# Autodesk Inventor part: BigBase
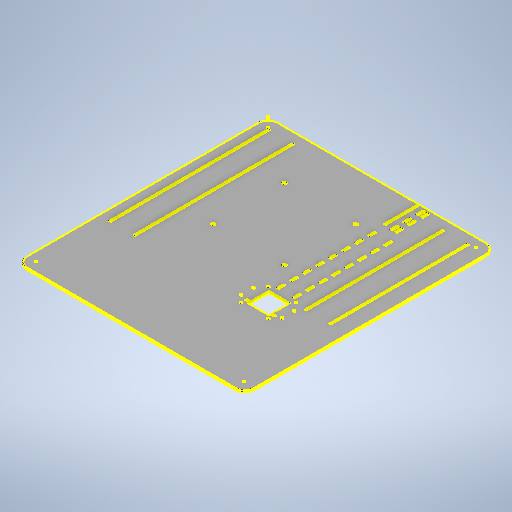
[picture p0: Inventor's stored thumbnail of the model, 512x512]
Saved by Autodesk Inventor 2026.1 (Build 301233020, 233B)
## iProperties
Created: 2026-10
Part Number: BigBase
Material: Generic
Document SubType Name: Modeling
Designer: hp
Density: 1 g/cm^3
Appearance: Default
Author: hp
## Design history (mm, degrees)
sketch "BigBaseSketch"
  geometry: L1 (0, 0)-(1200, 0); L2 (1200, 0)-(1200, 700); L3 (1200, 700)-(0, 700); L4 (0, 700)-(0, 0); L5 (378, 191.5)-(141, 191.5); L6 (141, 191.5)-(141, 428.5); L7 (141, 428.5)-(378, 428.5); L8 (378, 428.5)-(378, 191.5); L9 (378, 191.5)-(141, 428.5); L10 (141, 191.5)-(378, 428.5); L11 (259.5, 191.5)-(259.5, 428.5); L12 (378, 310)-(141, 310); L13 (141, 310)-(378, 310); C1 r 5 at (150, 200.5); C2 r 5 at (150, 419.5); C3 r 5 at (369, 200.5); C4 r 5 at (369, 419.5); 1 further point
  constraints: 26 end point, 5 midpoint, 5 symmetric about line, 4 centre point, 4 parallel, 2 horizontal, 2 perpendicular, 1 point on line, 3 other
  dimensions: "d0" = 1200 distance of L3.end L2.end; "d236" = 237 distance of L6.end L7.end; "d237" = 237 distance of L5.end L6.end; "d242" = 10 diameter of C1; "d243" = 9 distance from line of L5 C1.centre; "d245" = 150 distance from line of L4 C1.centre; "d252" = 700 distance of L3.end L1.start; "d253" = 40 vertical distance of point (0, 350) L12.end
extrude "Extrusion2" new body sketch "BigBaseSketch" distance "d14" = 5; taper "d15" = 0 deg
sketch "Sketch3"
  geometry: L1 (31, -10)-(31, 630); L2 (31, 106.5)-(521, 106.5); L3 (521, 106.5)-(521, 111.5); L4 (521, 111.5)-(31, 111.5); L5 (31, 111.5)-(31, 106.5); L6 (31, 31.5)-(521, 31.5); L7 (521, 31.5)-(521, 36.5); L8 (521, 36.5)-(31, 36.5); L9 (31, 36.5)-(31, 31.5); L10 (31, 568.5)-(456, 568.5); L11 (456, 568.5)-(456, 573.5); L12 (456, 573.5)-(31, 573.5); L13 (31, 573.5)-(31, 568.5); L14 (31, 643.5)-(456, 643.5); L15 (456, 648.5)-(31, 648.5); L16 (456, 643.5)-(456, 648.5); L17 (31, 648.5)-(31, 643.5); L18 (378, 191.5)-(141, 191.5) reference; L19 (141, 191.5)-(141, 428.5) reference; L20 (141, 428.5)-(378, 428.5) reference; L21 (378, 428.5)-(378, 191.5) reference; L22 (259.5, 191.5)-(259.5, 428.5) reference; L23 (0, 700)-(0, 0) reference; L24 (131, 468.5)-(461, 468.5); L25 (461, 468.5)-(461, 523.5); L26 (461, 523.5)-(131, 523.5); L27 (131, 523.5)-(131, 468.5); L28 (131, 468.5)-(461, 468.5); L29 (461, 468.5)-(461, 473.5); L30 (461, 473.5)-(131, 473.5); L31 (131, 473.5)-(131, 468.5); L32 (131, 523.5)-(461, 523.5); L33 (461, 523.5)-(461, 518.5); L34 (461, 518.5)-(131, 518.5); L35 (131, 518.5)-(131, 523.5); 3 further points; 2 other entities
  constraints: 58 end point, 14 parallel, 7 horizontal, 7 perpendicular, 4 collinear, 2 midpoint, 2 point on line, 1 horizontal alignment, 2 other
  dimensions: "d64" = 640 distance of L1.end L1.start; "d129" = 490 distance of L4.end L3.end; "d130" = 5 distance of L3.end L2.end; "d133" = 490 distance of L8.end L7.end (derived); "d134" = 5 distance of L7.end L6.end; "d135" = 70 distance between parallel lines of L2 L8; "d138" = 425 distance of L12.end L11.end; "d139" = 5 distance of L11.end L10.end; "d140" = 425 distance of L15.end L15.start (derived); "d141" = 5 distance of L15.start L14.end; "d144" = 70 distance between parallel lines of L12 L14; "d248" = 80 distance between parallel lines of L4 L18; "d249" = 140 distance between parallel lines of L20 L10; "d251" = 31 distance between parallel lines of L1 L23; "d259" = 330 distance of L26.end L25.end; "d260" = 55 distance of L25.end L24.end; "d261" = 40 distance between parallel lines of L20 L24; "d262" = 5 distance between parallel lines of L11 L25; "d263" = 5 distance of L29.end L28.end; "d264" = 5 distance of L32.end L33.end
extrude "Extrusion3" cut sketch "Sketch3" extent not by distance; stored distance "d101" = 0; taper "d102" = 0 deg
sketch "Sketch20"
  geometry: 4 further points
hole "Hole8" sketch "Sketch20" at (-477, 433.5), (-515, 433.5), (-477, 558.5), (-515, 558.5) diameter "d331" = 4.5; stored, may be unused: countersink angle "d335" = 90 deg, drill point angle "d337" = 0 deg; dims "d332" = 6, "d333" = 4, "d334" = 2, "d336" = 8
sketch "Sketch4"
  geometry: L1 (526, 463.5)-(526, 528.5); L2 (526, 528.5)-(461, 528.5); L3 (461, 528.5)-(461, 463.5); L4 (461, 463.5)-(526, 463.5); L5 (378, 428.5)-(378, 191.5) reference; L6 (378, 191.5)-(141, 191.5) reference; L7 (461, 468.5)-(461, 523.5) reference; 1 further point
  constraints: 8 end point, 2 parallel, 1 perpendicular
  dimensions: "d119" = 65 distance of L3.end L2.end; "d120" = 65 distance of L2.end L1.end; "d330" = 83 distance between parallel lines of L5 L3
extrude "Extrusion4" cut sketch "Sketch4" extent not by distance; stored distance "d112" = 0; taper "d113" = 0 deg
fillet "Fillet1" dims "d147" = 30
extrude "Extrusion7" cut sketch "BigBaseSketch" distance "d246" = 5; taper "d247" = 0 deg
sketch "Sketch16"
  geometry: L1 (131, 468.5)-(461, 468.5) reference; L2 (461, 473.5)-(131, 473.5) reference; L3 (461, 518.5)-(131, 518.5) reference; L4 (131, 523.5)-(461, 523.5) reference; L5 (131, 523.5)-(131, 468.5) reference; L6 (461, 468.5)-(461, 523.5) reference; L7 (141, 468.5)-(161, 468.5); L8 (161, 468.5)-(161, 473.5); L9 (161, 473.5)-(141, 473.5); L10 (141, 473.5)-(141, 468.5); L11 (141, 518.5)-(161, 518.5); L12 (161, 518.5)-(161, 523.5); L13 (161, 523.5)-(141, 523.5); L14 (141, 523.5)-(141, 518.5); L15 (181, 473.5)-(181, 468.5); L16 (181, 468.5)-(201, 468.5); L17 (201, 473.5)-(181, 473.5); L18 (201, 468.5)-(201, 473.5); L19 (181, 518.5)-(201, 518.5); L20 (181, 523.5)-(181, 518.5); L21 (201, 518.5)-(201, 523.5); L22 (201, 523.5)-(181, 523.5); L23 (221, 473.5)-(221, 468.5); L24 (221, 468.5)-(241, 468.5); L25 (241, 473.5)-(221, 473.5); L26 (241, 468.5)-(241, 473.5); L27 (221, 518.5)-(241, 518.5); L28 (221, 523.5)-(221, 518.5); L29 (241, 518.5)-(241, 523.5); L30 (241, 523.5)-(221, 523.5); L31 (261, 473.5)-(261, 468.5); L32 (261, 468.5)-(281, 468.5); L33 (281, 473.5)-(261, 473.5); L34 (281, 468.5)-(281, 473.5); L35 (261, 518.5)-(281, 518.5); L36 (261, 523.5)-(261, 518.5); L37 (281, 518.5)-(281, 523.5); L38 (281, 523.5)-(261, 523.5); L39 (301, 473.5)-(301, 468.5); L40 (301, 468.5)-(321, 468.5); L41 (321, 473.5)-(301, 473.5); L42 (321, 468.5)-(321, 473.5); L43 (301, 518.5)-(321, 518.5); L44 (301, 523.5)-(301, 518.5); L45 (321, 518.5)-(321, 523.5); L46 (321, 523.5)-(301, 523.5); L47 (341, 473.5)-(341, 468.5); L48 (341, 468.5)-(361, 468.5); L49 (361, 473.5)-(341, 473.5); L50 (361, 468.5)-(361, 473.5); L51 (341, 518.5)-(361, 518.5); L52 (341, 523.5)-(341, 518.5); L53 (361, 518.5)-(361, 523.5); L54 (361, 523.5)-(341, 523.5); L55 (381, 473.5)-(381, 468.5); L56 (381, 468.5)-(401, 468.5); L57 (401, 473.5)-(381, 473.5); L58 (401, 468.5)-(401, 473.5); L59 (381, 518.5)-(401, 518.5); L60 (381, 523.5)-(381, 518.5); L61 (401, 518.5)-(401, 523.5); L62 (401, 523.5)-(381, 523.5); L63 (421, 473.5)-(421, 468.5); L64 (421, 468.5)-(441, 468.5)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; 1 further point
  constraints: 128 end point, 4 parallel, 4 point on line, 3 horizontal, 2 perpendicular, 1 collinear, 112 other
  dimensions: "d274" = 20 distance of L9.end L8.end; "d275" = 10 distance between parallel lines of L5 L10; "d276" = 20 distance of L13.end L12.end; "d279" = 40 distance of L7.start L15.end
extrude "Extrusion8" cut sketch "Sketch16" distance "d284" = 5; taper "d285" = 0 deg
sketch "Sketch17"
  geometry: L1 (461, 528.5)-(526, 528.5) reference; L2 (461, 463.5)-(461, 528.5) reference; L3 (526, 528.5)-(526, 463.5) reference; L4 (526, 463.5)-(461, 463.5) reference; L5 (1170, 700)-(30, 700) reference; L6 (461, 700)-(526, 700); L7 (526, 700)-(526, 800); L8 (526, 800)-(461, 800); L9 (461, 800)-(461, 700); L10 (491.3, 590)-(498.5, 590); L11 (498.5, 590)-(498.5, 767); L12 (498.5, 767)-(491.3, 767); L13 (491.3, 767)-(491.3, 590); L14 (0, 492.4)-(121, 492.4); L15 (121, 492.4)-(121, 499.6); L16 (121, 499.6)-(0, 499.6); L17 (0, 499.6)-(0, 492.4); L18 (131, 523.5)-(131, 468.5) reference; L19 (0, 670)-(0, 30) reference; L20 (0, 499.6)-(121, 499.6); L21 (121, 499.6)-(121, 505.6); L22 (121, 505.6)-(0, 505.6); L23 (0, 505.6)-(0, 499.6); L24 (0, 492.4)-(121, 492.4); L25 (121, 492.4)-(121, 486.4); L26 (121, 486.4)-(0, 486.4); L27 (0, 486.4)-(0, 492.4); 6 further points
  constraints: 40 end point, 10 parallel, 5 horizontal, 5 perpendicular, 4 midpoint, 3 point on line, 1 collinear, 1 horizontal alignment
  dimensions: "d288" = 100 distance of L7.end L6.end; "d291" = 7.2 distance of L12.end L11.end; "d294" = 33 distance between parallel lines of L8 L12; "d295" = 210 distance from line of point (493.5, 800) L10; "d298" = 31.1 distance from line of L3 point (494.9, 590) (derived); "d306" = 7.2 distance of L15.end L14.end; "d307" = 10 distance of point (131, 496) point (121, 496); "d308" = 6 distance of L21.end L20.end; "d309" = 6 distance of L24.end L25.end (derived)
sketch "Sketch19"
  geometry: L1 (0, 670)-(0, 30) reference; L2 (121, 486.4)-(0, 486.4) reference; L3 (121, 505.6)-(0, 505.6) reference; L4 (121, 499.6)-(0, 499.6) reference; L5 (0, 492.4)-(121, 492.4) reference; L6 (121, 492.4)-(121, 486.4) reference; L7 (121, 499.6)-(121, 505.6) reference; L8 (10, 486.4)-(30, 486.4); L9 (30, 486.4)-(30, 492.4); L10 (30, 492.4)-(10, 492.4); L11 (10, 492.4)-(10, 486.4); L12 (10, 499.6)-(30, 499.6); L13 (30, 499.6)-(30, 505.6); L14 (30, 505.6)-(10, 505.6); L15 (10, 505.6)-(10, 499.6); L16 (10.1, 486.4)-(29.9, 486.4); L17 (29.9, 486.4)-(29.9, 492.4); L18 (29.9, 492.4)-(10.1, 492.4); L19 (10.1, 492.4)-(10.1, 486.4); L20 (10.1, 499.6)-(29.9, 499.6); L21 (29.9, 499.6)-(29.9, 505.6); L22 (29.9, 505.6)-(10.1, 505.6); L23 (10.1, 505.6)-(10.1, 499.6); L24 (50.1, 492.4)-(50.1, 486.4); L25 (50.1, 486.4)-(69.9, 486.4); L26 (50, 492.4)-(50, 486.4); L27 (50, 486.4)-(70, 486.4); L28 (69.9, 499.6)-(69.9, 505.6); L29 (70, 499.6)-(70, 505.6); L30 (69.9, 492.4)-(50.1, 492.4); L31 (70, 492.4)-(50, 492.4); L32 (50.1, 499.6)-(69.9, 499.6); L33 (50, 499.6)-(70, 499.6); L34 (69.9, 505.6)-(50.1, 505.6); L35 (70, 505.6)-(50, 505.6); L36 (50.1, 505.6)-(50.1, 499.6); L37 (50, 505.6)-(50, 499.6); L38 (69.9, 486.4)-(69.9, 492.4); L39 (70, 486.4)-(70, 492.4); L40 (90.1, 492.4)-(90.1, 486.4); L41 (90.1, 486.4)-(109.9, 486.4); L42 (90, 492.4)-(90, 486.4); L43 (90, 486.4)-(110, 486.4); L44 (109.9, 499.6)-(109.9, 505.6); L45 (110, 499.6)-(110, 505.6); L46 (109.9, 492.4)-(90.1, 492.4); L47 (110, 492.4)-(90, 492.4); L48 (90.1, 499.6)-(109.9, 499.6); L49 (90, 499.6)-(110, 499.6); L50 (109.9, 505.6)-(90.1, 505.6); L51 (110, 505.6)-(90, 505.6); L52 (90.1, 505.6)-(90.1, 499.6); L53 (90, 505.6)-(90, 499.6); L54 (109.9, 486.4)-(109.9, 492.4); L55 (110, 486.4)-(110, 492.4); 13 further points
  constraints: 96 end point, 8 parallel, 8 point on line, 5 horizontal, 4 midpoint, 4 perpendicular, 3 collinear, 2 coincident, 71 other
  dimensions: "d310" = 20 distance of L10.end L9.end; "d311" = 10 distance between parallel lines of L1 L11; "d321" = 19.8 distance of L18.end L17.end; "d322" = 19.8 distance of L22.end L21.end; "d325" = 40 distance of point (20, 492.4) point (60, 492.4)
extrude "Extrusion11" cut sketch "Sketch19" stored distance "d319" = 10; taper "d320" = 0 deg
sketch "Sketch21"
  geometry: L1 (1170, 700)-(30, 700) reference; L2 (1201.62, 0)-(771, 0); L3 (771, 0)-(771, 700); L4 (771, 700)-(1201.62, 700); L5 (1201.62, 700)-(1201.62, 0); L6 (521, 111.5)-(521, 106.5) reference; 2 further points
  constraints: 8 end point, 2 parallel, 1 horizontal, 1 perpendicular, 1 point on line
  dimensions: "d340" = 250 distance between parallel lines of L3 L6
extrude "Extrusion12" cut sketch "Sketch21" distance "d338" = 10; taper "d339" = 0 deg
fillet "Fillet2" dims "d341" = 30
sketch "Sketch22"
  geometry: L1 (5, 462.5)-(105, 462.5); L2 (105, 462.5)-(105, 467.5); L3 (105, 467.5)-(5, 467.5); L4 (5, 467.5)-(5, 462.5); L5 (0, 670)-(0, 30) reference; L6 (29.9, 486.4)-(10.1, 486.4) reference; 2 further points
  constraints: 8 end point, 2 parallel, 1 horizontal, 1 midpoint, 1 perpendicular
  dimensions: "d342" = 100 distance of L3.end L2.end; "d343" = 5 distance of L2.end L1.end; "d344" = 5 distance from line of L5 point (5, 465); "d345" = 18.9 distance between parallel lines of L6 L3
extrude "Extrusion13" cut sketch "Sketch22" distance "d346" = 5; taper "d347" = 0 deg
sketch "Sketch23"
  geometry: 4 further points
hole "Hole9" sketch "Sketch23" at (536, 538.5), (451, 538.5), (451, 453.5), (536, 453.5) diameter "d348" = 4.5; stored, may be unused: countersink angle "d352" = 90 deg, drill point angle "d354" = 0 deg; dims "d349" = 6, "d350" = 4, "d351" = 2, "d353" = 8
sketch "Sketch24"
  geometry: L1 (-105, 467.5)-(-5, 467.5) reference; L2 (-5, 467.5)-(-5, 462.5) reference; L3 (-5, 462.5)-(-105, 462.5) reference; L4 (-105, 462.5)-(-105, 467.5) reference; L5 (-771, 670)-(-771, 30) reference; L6 (-30, 0)-(-741, 0) reference; L7 (0, 670)-(0, 30) reference; L8 (-741, 700)-(-30, 700) reference; L9 (-69.9, 505.6)-(-50.1, 505.6) reference; L10 (-50.1, 505.6)-(-50.1, 499.6) reference; L11 (-50.1, 499.6)-(-69.9, 499.6) reference; L12 (-69.9, 499.6)-(-69.9, 505.6) reference; L13 (-109.9, 499.6)-(-109.9, 505.6) reference; L14 (-109.9, 505.6)-(-90.1, 505.6) reference; L15 (-90.1, 505.6)-(-90.1, 499.6) reference; L16 (-90.1, 499.6)-(-109.9, 499.6) reference; L17 (-90.1, 486.4)-(-109.9, 486.4) reference; L18 (-109.9, 486.4)-(-109.9, 492.4) reference; L19 (-109.9, 492.4)-(-90.1, 492.4) reference; L20 (-90.1, 492.4)-(-90.1, 486.4) reference; L21 (-10.1, 499.6)-(-29.9, 499.6) reference; L22 (-29.9, 499.6)-(-29.9, 505.6) reference; L23 (-29.9, 505.6)-(-10.1, 505.6) reference; L24 (-10.1, 505.6)-(-10.1, 499.6) reference; L25 (-50.1, 486.4)-(-69.9, 486.4) reference; L26 (-69.9, 486.4)-(-69.9, 492.4) reference; L27 (-69.9, 492.4)-(-50.1, 492.4) reference; L28 (-50.1, 492.4)-(-50.1, 486.4) reference; L29 (-10.1, 486.4)-(-29.9, 486.4) reference; L30 (-29.9, 486.4)-(-29.9, 492.4) reference; L31 (-29.9, 492.4)-(-10.1, 492.4) reference; L32 (-10.1, 492.4)-(-10.1, 486.4) reference; L33 (-321, 468.5)-(-321, 473.5) reference; L34 (-321, 473.5)-(-301, 473.5) reference; L35 (-301, 473.5)-(-301, 468.5) reference; L36 (-301, 468.5)-(-321, 468.5) reference; L37 (-361, 468.5)-(-361, 473.5) reference; L38 (-361, 473.5)-(-341, 473.5) reference; L39 (-341, 473.5)-(-341, 468.5) reference; L40 (-341, 468.5)-(-361, 468.5) reference; L41 (-401, 468.5)-(-401, 473.5) reference; L42 (-401, 473.5)-(-381, 473.5) reference; L43 (-381, 473.5)-(-381, 468.5) reference; L44 (-381, 468.5)-(-401, 468.5) reference; L45 (-441, 468.5)-(-441, 473.5) reference; L46 (-441, 473.5)-(-421, 473.5) reference; L47 (-421, 473.5)-(-421, 468.5) reference; L48 (-421, 468.5)-(-441, 468.5) reference; L49 (-161, 523.5)-(-141, 523.5) reference; L50 (-141, 523.5)-(-141, 518.5) reference; L51 (-141, 518.5)-(-161, 518.5) reference; L52 (-161, 518.5)-(-161, 523.5) reference; L53 (-201, 523.5)-(-181, 523.5) reference; L54 (-181, 523.5)-(-181, 518.5) reference; L55 (-181, 518.5)-(-201, 518.5) reference; L56 (-201, 518.5)-(-201, 523.5) reference; L57 (-241, 523.5)-(-221, 523.5) reference; L58 (-221, 523.5)-(-221, 518.5) reference; L59 (-221, 518.5)-(-241, 518.5) reference; L60 (-241, 518.5)-(-241, 523.5) reference; L61 (-281, 523.5)-(-261, 523.5) reference; L62 (-261, 523.5)-(-261, 518.5) reference; L63 (-261, 518.5)-(-281, 518.5) reference; L64 (-281, 518.5)-(-281, 523.5) reference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; C1 r 2.25 at (-536, 453.5) reference; C2 r 2.25 at (-451, 453.5) reference; C3 r 2.25 at (-451, 538.5) reference; C4 r 2.25 at (-536, 538.5) reference; C5 r 5 at (-369, 200.5) reference; C6 r 5 at (-150, 419.5) reference; C7 r 5 at (-369, 419.5) reference; C8 r 5 at (-150, 200.5) reference; C9 r 2.25 at (-515, 558.5) reference; C10 r 2.25 at (-477, 558.5) reference; C11 r 2.25 at (-515, 433.5) reference; C12 r 2.25 at (-477, 433.5) reference; A1 r 30 centre (-741, 670) between (-741, 700) and (-771, 670) reference; A2 r 30 centre (-741, 30) between (-771, 30) and (-741, 0) reference; A3 r 30 centre (-30, 30) between (-30, 0) and (0, 30) reference; A4 r 30 centre (-30, 670) between (0, 670) and (-30, 700) reference; 1 further point
  node "Projected Loop2"
sketch "Sketch25"
  geometry: L1 (526, 528.5)-(526, 463.5) reference; L2 (526, 463.5)-(461, 463.5) reference; L3 (461, 528.5)-(526, 528.5) reference; L4 (461, 463.5)-(461, 528.5) reference; L5 (521, 461)-(516, 461); L6 (516, 461)-(516, 451.2); L7 (516, 451.2)-(521, 451.2); L8 (521, 451.2)-(521, 461); L9 (516, 531)-(521, 531); L10 (521, 531)-(521, 540.8); L11 (521, 540.8)-(516, 540.8); L12 (516, 540.8)-(516, 531); 1 further point
  constraints: 16 end point, 4 parallel, 2 horizontal, 2 perpendicular, 2 point on line
  dimensions: "d355" = 5 distance of L7.end L6.end; "d356" = 9.8 distance of L6.end L5.end; "d357" = 9.8 distance of L10.end L9.end; "d358" = 5 distance between parallel lines of L1 L10; "d359" = 2.5 distance between parallel lines of L3 L9; "d360" = 2.5 distance between parallel lines of L5 L2 (derived)
extrude "Extrusion14" cut sketch "Sketch25" stored distance "d361" = 5; taper "d362" = 0 deg
sketch "Sketch26"
  geometry: L1 (521, 540.8)-(521, 531) reference; L2 (521, 531)-(516, 531) reference; L3 (516, 531)-(516, 540.8) reference; L4 (516, 540.8)-(521, 540.8) reference; L5 (516, 461)-(521, 461) reference; L6 (521, 461)-(521, 451.2) reference; L7 (521, 451.2)-(516, 451.2) reference; L8 (516, 451.2)-(516, 461) reference; L9 (5, 467.5)-(105, 467.5) reference; L10 (105, 467.5)-(105, 462.5) reference; L11 (105, 462.5)-(5, 462.5) reference; L12 (5, 462.5)-(5, 467.5) reference; L13 (31, 573.5)-(456, 573.5) reference; L14 (456, 573.5)-(456, 568.5) reference; L15 (456, 568.5)-(31, 568.5) reference; L16 (31, 568.5)-(31, 573.5) reference; L17 (31, 111.5)-(521, 111.5) reference; L18 (521, 111.5)-(521, 106.5) reference; L19 (521, 106.5)-(31, 106.5) reference; L20 (31, 106.5)-(31, 111.5) reference; L21 (31, 648.5)-(456, 648.5) reference; L22 (456, 648.5)-(456, 643.5) reference; L23 (456, 643.5)-(31, 643.5) reference; L24 (31, 643.5)-(31, 648.5) reference; L25 (31, 36.5)-(521, 36.5) reference; L26 (521, 36.5)-(521, 31.5) reference; L27 (521, 31.5)-(31, 31.5) reference; L28 (31, 31.5)-(31, 36.5) reference; L29 (461, 463.5)-(461, 528.5) reference; L30 (461, 528.5)-(526, 528.5) reference; L31 (526, 528.5)-(526, 463.5) reference; L32 (526, 463.5)-(461, 463.5) reference; L33 (741, 700)-(30, 700) reference; L34 (0, 670)-(0, 30) reference; L35 (30, 0)-(741, 0) reference; L36 (771, 30)-(771, 670) reference; L37 (421, 523.5)-(441, 523.5) reference; L38 (441, 523.5)-(441, 518.5) reference; L39 (441, 518.5)-(421, 518.5) reference; L40 (421, 518.5)-(421, 523.5) reference; L41 (301, 523.5)-(321, 523.5) reference; L42 (321, 523.5)-(321, 518.5) reference; L43 (321, 518.5)-(301, 518.5) reference; L44 (301, 518.5)-(301, 523.5) reference; L45 (341, 523.5)-(361, 523.5) reference; L46 (361, 523.5)-(361, 518.5) reference; L47 (361, 518.5)-(341, 518.5) reference; L48 (341, 518.5)-(341, 523.5) reference; L49 (381, 523.5)-(401, 523.5) reference; L50 (401, 523.5)-(401, 518.5) reference; L51 (401, 518.5)-(381, 518.5) reference; L52 (381, 518.5)-(381, 523.5) reference; L53 (141, 473.5)-(161, 473.5) reference; L54 (161, 473.5)-(161, 468.5) reference; L55 (161, 468.5)-(141, 468.5) reference; L56 (141, 468.5)-(141, 473.5) reference; L57 (201, 473.5)-(201, 468.5) reference; L58 (201, 468.5)-(181, 468.5) reference; L59 (181, 468.5)-(181, 473.5) reference; L60 (181, 473.5)-(201, 473.5) reference; L61 (241, 473.5)-(241, 468.5) reference; L62 (241, 468.5)-(221, 468.5) reference; L63 (221, 468.5)-(221, 473.5) reference; L64 (221, 473.5)-(241, 473.5) reference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; C1 r 2.25 at (536, 453.5) reference; C2 r 2.25 at (451, 453.5) reference; C3 r 2.25 at (451, 538.5) reference; C4 r 2.25 at (536, 538.5) reference; C5 r 2.25 at (477, 433.5) reference; C6 r 2.25 at (515, 433.5) reference; C7 r 2.25 at (477, 558.5) reference; C8 r 2.25 at (515, 558.5) reference; C9 r 5 at (150, 200.5) reference; C10 r 5 at (369, 419.5) reference; C11 r 5 at (150, 419.5) reference; C12 r 5 at (369, 200.5) reference; A1 r 30 centre (741, 670) between (771, 670) and (741, 700) reference; A2 r 30 centre (30, 670) between (30, 700) and (0, 670) reference; A3 r 30 centre (30, 30) between (0, 30) and (30, 0) reference; A4 r 30 centre (741, 30) between (741, 0) and (771, 30) reference; 1 further point
  node "Projected Loop3"
body "Solid2"
node "Sketch Rectangular Pattern6" dims "d279" = 40, "d282" = 10
node "Sketch Rectangular Pattern8" dims "d325" = 40, "d328" = 10
other parameters: "d110" = 63
